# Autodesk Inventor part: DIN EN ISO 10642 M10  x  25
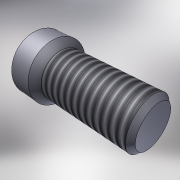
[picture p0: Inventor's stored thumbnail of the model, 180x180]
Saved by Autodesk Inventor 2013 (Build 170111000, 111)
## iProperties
Created: 2012-02
Part Number: DIN EN ISO 10642 M10  x  25
Material: Generic
Document SubType Name: Modeling
Designer: tedescj
Density: 1 g/cm^3
Mass: 2.10791 g
Surface Area: 11.3576 cm^2
Volume: 2.10791 cm^3
Translation Standard: STEP AP214IS
FileName: D:\_Workspace\Dropbox\Launch 2013, Inprocess\Front Loader, CIS\_Data\M10-6gx25.58.019.stp
PreProcessor: Autodesk Inventor 2012
PostProcessor: Build: 190, Release: 2012 SP1 - Date: Mon 08/08/2011
Sent Units: millimeter
Uncertainty: 0.01
Author: tedescj
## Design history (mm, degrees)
feature "Base1"
thread "Thread1" dims "d0" = 12, "d1" = 0
body "Solid1"
